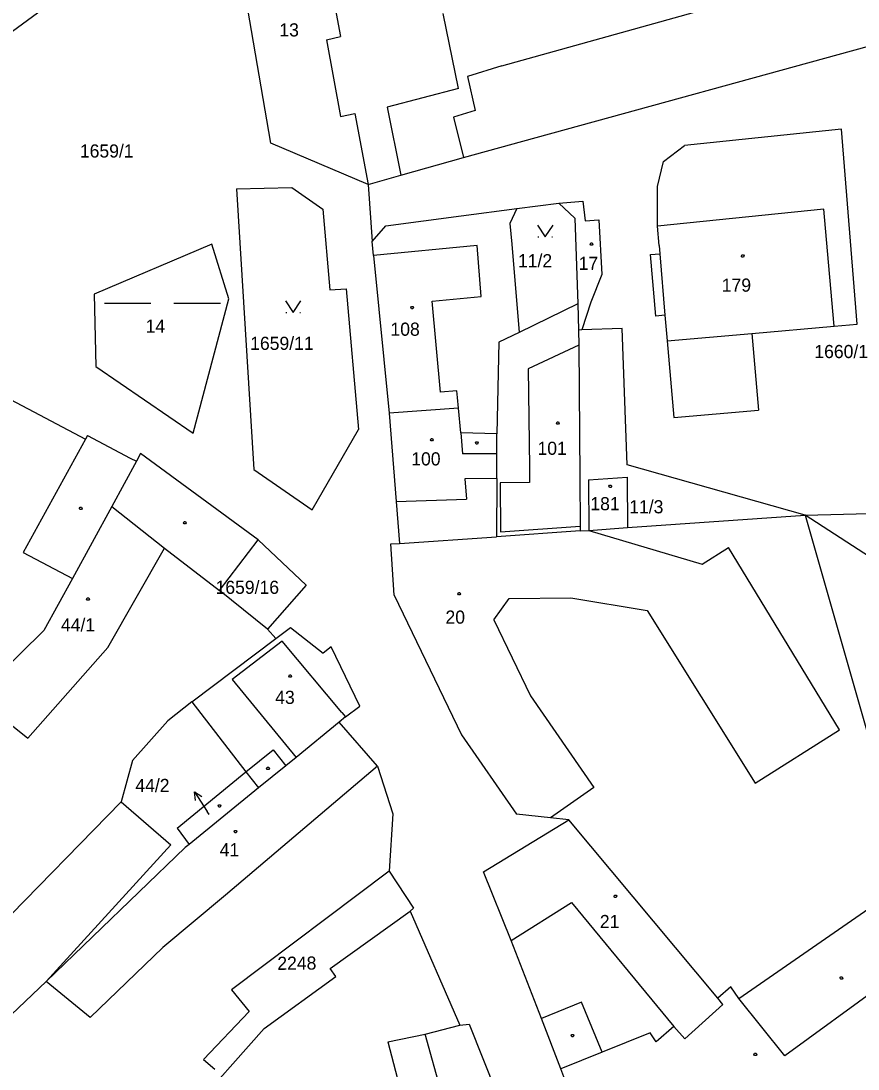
# Model space of a CAD drawing. Extents: x -802857 to -799647, y -1020285 to -1015884.
# Drawn here: x -801501.8 to -801393.5, y -1017775.9 to -1017640.2 of the extents above; entities that cross this region are included whole.
import ezdxf

# ---------------------------------------------------------------- set-up
doc = ezdxf.new("R2010")
doc.units = 0
for name, color, linetype in [('Default', 7, 'Continuous'), ('KN_HRANICE', 7, 'Continuous'), ('KN_KULTURY', 7, 'Continuous'), ('KN_PARCELY', 7, 'Continuous'), ('KN_SLUCKY', 7, 'Continuous')]:
    doc.layers.add(name, color=color, linetype=linetype)

# ---------------------------------------------------------------- blocks, each defined once
blk = doc.blocks.new('314')
at = {"layer": 'Default'}
for p, q in [((-0.95, 0), (-0.85, 0)), ((0.85, 0), (0.95, 0))]:
    blk.add_line(p, q, dxfattribs=at)
blk.add_lwpolyline([(-1, 1.5), (0, 0), (1, 1.5)], dxfattribs=at)
blk = doc.blocks.new('NAHRADNI_SYMBOL')
at = {"layer": 'Default'}
blk.add_lwpolyline([(0.09, 0.15), (0.18, 0), (0.09, -0.15), (-0.09, -0.15), (-0.18, 0), (-0.09, 0.15), (0.09, 0.15)], dxfattribs=at)
blk = doc.blocks.new('803')
at = {"layer": 'Default'}
for p, q in [((-7.5, 0), (-1.5, 0)), ((1.5, 0), (7.5, 0))]:
    blk.add_line(p, q, dxfattribs=at)
blk = doc.blocks.new('10292')
at = {"layer": 'Default'}
blk.add_line((0, 3), (0, 0), dxfattribs=at)
blk.add_lwpolyline([(-0.5, 2), (0, 3), (0.5, 2)], dxfattribs=at)
blk = doc.blocks.new('402')
at = {"layer": 'Default'}
blk.add_lwpolyline([(0.09, 0.15), (0.18, 0), (0.09, -0.15), (-0.09, -0.15), (-0.18, 0), (-0.09, 0.15), (0.09, 0.15)], dxfattribs=at)

msp = doc.modelspace()

# ---------------------------------------------------------------- linework, layer by layer
at = {"layer": 'KN_HRANICE'}
for p, q in [((-801439.56, -1017646.05), (-801339.49, -1017618.1)), ((-801464.55, -1017620.59), (-801460.47, -1017642.27)), ((-801469.47, -1017656.08), (-801475.13, -1017623.23)), ((-801436.88, -1017655.78), (-801344.28, -1017630.37)), ((-801499.03, -1017638.78), (-801510.49, -1017647.16)), ((-801445.17, -1017648.98), (-801447.15, -1017639.26)), ((-801462.26, -1017642.67), (-801460.47, -1017642.27)), ((-801462.26, -1017642.67), (-801460.46, -1017652.61)), ((-801439.56, -1017646.05), (-801444.04, -1017647.45)), ((-801444.04, -1017647.45), (-801443.02, -1017651.83)), ((-801445.17, -1017648.98), (-801454.4, -1017651.38)), ((-801460.46, -1017652.61), (-801458.6, -1017652.2)), ((-801458.6, -1017652.2), (-801456.87, -1017661.39)), ((-801454.4, -1017651.38), (-801452.65, -1017660.21)), ((-801443.02, -1017651.83), (-801445.83, -1017652.69)), ((-801445.83, -1017652.69), (-801444.54, -1017657.93)), ((-801395.62, -1017654.26), (-801415.94, -1017656.38)), ((-801393.58, -1017679.48), (-801395.62, -1017654.26)), ((-801456.87, -1017661.39), (-801469.47, -1017656.08)), ((-801444.54, -1017657.93), (-801436.88, -1017655.78)), ((-801418.65, -1017658.44), (-801415.94, -1017656.38)), ((-801452.65, -1017660.21), (-801444.54, -1017657.93)), ((-801419.45, -1017661.66), (-801418.65, -1017658.44)), ((-801456.87, -1017661.39), (-801452.65, -1017660.21)), ((-801473.9, -1017661.96), (-801466.75, -1017661.81)), ((-801473.9, -1017661.96), (-801471.67, -1017698.28)), ((-801466.75, -1017661.81), (-801462.75, -1017664.58)), ((-801456.87, -1017661.39), (-801456.38, -1017668.8)), ((-801419.44, -1017665.46), (-801419.45, -1017661.66)), ((-801462.75, -1017664.58), (-801461.83, -1017675.05)), ((-801444.82, -1017665.47), (-801437.64, -1017664.53)), ((-801437.64, -1017664.53), (-801438.53, -1017666.45)), ((-801437.64, -1017664.53), (-801432.19, -1017663.81)), ((-801432.19, -1017663.81), (-801429.11, -1017663.56)), ((-801432.19, -1017663.81), (-801430.14, -1017665.75)), ((-801429.11, -1017663.56), (-801428.81, -1017666.12)), ((-801454.57, -1017666.75), (-801444.82, -1017665.47)), ((-801430.14, -1017665.75), (-801429.73, -1017676.83)), ((-801428.81, -1017666.12), (-801427.01, -1017665.96)), ((-801427.01, -1017665.96), (-801426.65, -1017673.07)), ((-801419.44, -1017666.81), (-801419.44, -1017665.46)), ((-801456.38, -1017668.8), (-801454.57, -1017666.75)), ((-801438.53, -1017666.45), (-801438.3, -1017669.15)), ((-801419.23, -1017669.3), (-801419.44, -1017666.81)), ((-801456.2, -1017670.59), (-801456.38, -1017668.8)), ((-801477.13, -1017669.12), (-801492.36, -1017675.58)), ((-801474.9, -1017676.19), (-801477.13, -1017669.12)), ((-801438.3, -1017669.15), (-801437.35, -1017680.56)), ((-801419.23, -1017669.3), (-801419.14, -1017670.36)), ((-801456.2, -1017670.59), (-801454.16, -1017690.99)), ((-801420.34, -1017670.46), (-801419.14, -1017670.36)), ((-801419.66, -1017678.43), (-801420.34, -1017670.46)), ((-801426.65, -1017673.07), (-801428.05, -1017676.64)), ((-801492.36, -1017675.58), (-801492.13, -1017684.97)), ((-801461.83, -1017675.05), (-801459.74, -1017674.9)), ((-801459.74, -1017674.9), (-801458.13, -1017693.12)), ((-801479.51, -1017693.58), (-801474.9, -1017676.19)), ((-801429.73, -1017676.83), (-801437.35, -1017680.56)), ((-801429.73, -1017676.83), (-801429.65, -1017680.25)), ((-801428.05, -1017676.64), (-801429.23, -1017680.23)), ((-801418.46, -1017678.33), (-801419.66, -1017678.43)), ((-801418.46, -1017678.33), (-801418.18, -1017681.62)), ((-801407.22, -1017680.67), (-801396.57, -1017679.74)), ((-801396.57, -1017679.74), (-801393.58, -1017679.48)), ((-801437.35, -1017680.56), (-801439.98, -1017681.83)), ((-801429.23, -1017680.23), (-801429.65, -1017680.25)), ((-801429.65, -1017680.25), (-801429.62, -1017682.21)), ((-801424.02, -1017680.04), (-801429.23, -1017680.23)), ((-801423.35, -1017697.69), (-801424.02, -1017680.04)), ((-801407.22, -1017680.67), (-801406.35, -1017690.63)), ((-801439.98, -1017681.83), (-801440.22, -1017693.66)), ((-801429.62, -1017682.21), (-801429.47, -1017699.34)), ((-801418.18, -1017681.62), (-801417.31, -1017691.58)), ((-801492.13, -1017684.97), (-801479.51, -1017693.58)), ((-801503.16, -1017689.24), (-801493.48, -1017694.38)), ((-801445.17, -1017690.35), (-801454.16, -1017690.99)), ((-801444.9, -1017693.53), (-801445.17, -1017690.35)), ((-801417.31, -1017691.58), (-801406.35, -1017690.63)), ((-801454.16, -1017690.99), (-801453.25, -1017702.44)), ((-801464.13, -1017703.51), (-801458.13, -1017693.12)), ((-801493.2, -1017693.88), (-801493.48, -1017694.38)), ((-801493.2, -1017693.88), (-801487.66, -1017696.81)), ((-801444.9, -1017693.53), (-801444.66, -1017696.24)), ((-801440.21, -1017696.24), (-801440.22, -1017693.66)), ((-801486.87, -1017697.21), (-801490.05, -1017703.09)), ((-801487.66, -1017696.81), (-801486.87, -1017697.21)), ((-801486.33, -1017696.21), (-801486.87, -1017697.21)), ((-801471.12, -1017707.39), (-801486.33, -1017696.21)), ((-801440.21, -1017696.24), (-801444.66, -1017696.24)), ((-801440.22, -1017698), (-801440.21, -1017696.24)), ((-801471.67, -1017698.28), (-801464.13, -1017703.51)), ((-801440.23, -1017699.44), (-801440.22, -1017698)), ((-801400.33, -1017704.19), (-801423.35, -1017697.69)), ((-801440.23, -1017699.44), (-801440.25, -1017706.98)), ((-801429.47, -1017699.34), (-801429.43, -1017705.64)), ((-801428.36, -1017699.63), (-801423.34, -1017699.29)), ((-801428.36, -1017699.63), (-801428.32, -1017706.16)), ((-801423.34, -1017699.29), (-801423.32, -1017705.79)), ((-801453.25, -1017702.44), (-801452.8, -1017707.85)), ((-801490.05, -1017703.09), (-801495.16, -1017712.38)), ((-801423.32, -1017705.79), (-801400.33, -1017704.19)), ((-801400.33, -1017704.19), (-801384.4, -1017703.77)), ((-801400.33, -1017704.19), (-801386.84, -1017751.44)), ((-801380.71, -1017716.88), (-801400.33, -1017704.19)), ((-801429.43, -1017706.24), (-801440.25, -1017706.98)), ((-801429.43, -1017705.64), (-801429.43, -1017706.24)), ((-801429.43, -1017706.24), (-801428.32, -1017706.16)), ((-801428.32, -1017706.16), (-801423.32, -1017705.79)), ((-801476.12, -1017713.95), (-801471.12, -1017707.39)), ((-801471.12, -1017707.39), (-801464.92, -1017713.27)), ((-801453.96, -1017707.92), (-801452.8, -1017707.85)), ((-801453.53, -1017714.55), (-801453.96, -1017707.92)), ((-801452.8, -1017707.85), (-801440.25, -1017706.98)), ((-801495.16, -1017712.38), (-801498.85, -1017719.1)), ((-801464.92, -1017713.27), (-801469.89, -1017718.97)), ((-801469.89, -1017718.97), (-801476.12, -1017713.95)), ((-801453.53, -1017714.55), (-801444.8, -1017732.63)), ((-801498.85, -1017719.1), (-801507.61, -1017727.7)), ((-801469.89, -1017718.97), (-801468.81, -1017720.17)), ((-801468.81, -1017720.17), (-801466.92, -1017718.75)), ((-801466.92, -1017718.75), (-801462.68, -1017722.04)), ((-801479.69, -1017728.34), (-801468.81, -1017720.17)), ((-801461.67, -1017721.24), (-801462.68, -1017722.04)), ((-801457.95, -1017728.92), (-801461.67, -1017721.24)), ((-801479.69, -1017728.34), (-801482.8, -1017730.8)), ((-801479.69, -1017728.34), (-801472.69, -1017737.41)), ((-801459.8, -1017730.31), (-801457.95, -1017728.92)), ((-801482.8, -1017730.8), (-801487.38, -1017735.95)), ((-801460.64, -1017731), (-801466.21, -1017735.54)), ((-801459.8, -1017730.31), (-801460.64, -1017731)), ((-801455.66, -1017736.67), (-801460.64, -1017731)), ((-801444.8, -1017732.63), (-801437.69, -1017742.9)), ((-801487.38, -1017735.95), (-801488.83, -1017741.31)), ((-801467.55, -1017736.63), (-801471.07, -1017739.5)), ((-801466.21, -1017735.54), (-801467.55, -1017736.63)), ((-801455.66, -1017736.67), (-801453.7, -1017742.86)), ((-801472.69, -1017737.41), (-801471.07, -1017739.5)), ((-801471.07, -1017739.5), (-801480.05, -1017746.82)), ((-801488.83, -1017741.31), (-801482.4, -1017746.87)), ((-801453.7, -1017742.86), (-801454.14, -1017750.26)), ((-801433.27, -1017743.36), (-801437.69, -1017742.9)), ((-801430.91, -1017743.61), (-801433.27, -1017743.36)), ((-801441.93, -1017750.37), (-801430.91, -1017743.61)), ((-801411.64, -1017766.72), (-801430.91, -1017743.61)), ((-801482.4, -1017746.87), (-801498.56, -1017764.53)), ((-801480.55, -1017747.22), (-801498.56, -1017764.53)), ((-801480.05, -1017746.82), (-801480.55, -1017747.22)), ((-801454.14, -1017750.26), (-801474.58, -1017765.6)), ((-801454.14, -1017750.26), (-801451, -1017755.07)), ((-801438.38, -1017759.22), (-801441.93, -1017750.37)), ((-801451, -1017755.07), (-801451.46, -1017755.42)), ((-801451.46, -1017755.42), (-801445.03, -1017770.19)), ((-801434.46, -1017769.34), (-801438.38, -1017759.22)), ((-801384.3, -1017760.57), (-801402.96, -1017774.15)), ((-801498.56, -1017764.53), (-801505.81, -1017771.41)), ((-801409.95, -1017765.22), (-801411.64, -1017766.72)), ((-801408.92, -1017766.74), (-801409.95, -1017765.22)), ((-801474.58, -1017765.6), (-801472.28, -1017768.42)), ((-801415.89, -1017771.96), (-801410.96, -1017767.53)), ((-801410.96, -1017767.53), (-801411.64, -1017766.72)), ((-801402.96, -1017774.15), (-801408.92, -1017766.74)), ((-801472.28, -1017768.42), (-801478.17, -1017774.62)), ((-801449.49, -1017771.37), (-801445.03, -1017770.19)), ((-801445.03, -1017770.19), (-801443.81, -1017770.05)), ((-801443.81, -1017770.05), (-801439.99, -1017779.67)), ((-801431.94, -1017775.86), (-801434.46, -1017769.34)), ((-801417.3, -1017770.37), (-801419.61, -1017772.37)), ((-801417.3, -1017770.37), (-801415.89, -1017771.96)), ((-801454.34, -1017772.35), (-801449.49, -1017771.37)), ((-801420.38, -1017771.18), (-801426.59, -1017773.69)), ((-801419.61, -1017772.37), (-801420.38, -1017771.18)), ((-801454.34, -1017772.35), (-801451.15, -1017784.39)), ((-801478.17, -1017774.62), (-801476.71, -1017775.88)), ((-801426.59, -1017773.69), (-801431.94, -1017775.86)), ((-801428.76, -1017784.1), (-801431.94, -1017775.86))]:
    msp.add_line(p, q, dxfattribs=at)
msp.add_lwpolyline([(-801480.11, -1017781.68), (-801470.32, -1017770.64), (-801461.06, -1017763.9), (-801461.81, -1017762.88), (-801451.46, -1017755.42)], dxfattribs=at)
at = {"layer": 'KN_PARCELY'}
msp.add_line((-801477.47, -1017742.93), (-801477.73, -1017742.53), dxfattribs=at)
at = {"layer": 'KN_SLUCKY'}
for p, q in [((-801397.89, -1017664.58), (-801419.44, -1017666.81)), ((-801397.68, -1017667.07), (-801397.89, -1017664.58)), ((-801396.57, -1017679.74), (-801397.68, -1017667.07)), ((-801442.79, -1017669.32), (-801456.2, -1017670.59)), ((-801442.23, -1017675.92), (-801442.79, -1017669.32)), ((-801419.14, -1017670.36), (-801418.46, -1017678.33)), ((-801448.61, -1017676.52), (-801442.23, -1017675.92)), ((-801447.51, -1017688.29), (-801448.61, -1017676.52)), ((-801418.18, -1017681.62), (-801407.22, -1017680.67)), ((-801429.62, -1017682.21), (-801436.16, -1017685.24)), ((-801436.16, -1017685.24), (-801436.01, -1017697.99)), ((-801445.41, -1017688.09), (-801447.51, -1017688.29)), ((-801445.33, -1017688.99), (-801445.41, -1017688.09)), ((-801445.17, -1017690.35), (-801445.33, -1017688.99)), ((-801493.48, -1017694.38), (-801501.51, -1017709.02)), ((-801440.22, -1017693.66), (-801444.9, -1017693.53)), ((-801436.01, -1017697.99), (-801435.99, -1017699.99)), ((-801440.23, -1017699.44), (-801444.38, -1017699.5)), ((-801444.38, -1017699.5), (-801444.15, -1017702.13)), ((-801435.99, -1017699.99), (-801439.78, -1017700.01)), ((-801439.78, -1017700.01), (-801439.74, -1017706.34)), ((-801453.25, -1017702.44), (-801444.15, -1017702.13)), ((-801490.05, -1017703.09), (-801483.23, -1017708.46)), ((-801439.74, -1017706.34), (-801429.43, -1017705.64)), ((-801428.32, -1017706.16), (-801413.65, -1017710.55)), ((-801501.51, -1017709.02), (-801495.16, -1017712.38)), ((-801490.57, -1017721.33), (-801483.23, -1017708.46)), ((-801483.23, -1017708.46), (-801476.12, -1017713.95)), ((-801413.65, -1017710.55), (-801410.25, -1017708.4)), ((-801395.86, -1017731.97), (-801410.25, -1017708.4)), ((-801440.62, -1017717.72), (-801438.64, -1017714.97)), ((-801438.64, -1017714.97), (-801430.65, -1017714.89)), ((-801430.65, -1017714.89), (-801420.77, -1017716.55)), ((-801440.62, -1017717.72), (-801435.87, -1017727.56)), ((-801420.77, -1017716.55), (-801406.77, -1017738.86)), ((-801500.92, -1017733.04), (-801490.57, -1017721.33)), ((-801468, -1017720.51), (-801474.46, -1017725.46)), ((-801460.29, -1017729.75), (-801468, -1017720.51)), ((-801474.46, -1017725.46), (-801466.21, -1017735.54)), ((-801507.61, -1017727.7), (-801500.92, -1017733.04)), ((-801435.87, -1017727.56), (-801427.66, -1017739.42)), ((-801460.29, -1017729.75), (-801459.8, -1017730.31)), ((-801406.77, -1017738.86), (-801395.86, -1017731.97)), ((-801472.69, -1017737.41), (-801469.19, -1017734.55)), ((-801469.19, -1017734.55), (-801467.55, -1017736.63)), ((-801455.66, -1017736.67), (-801475.36, -1017753.35)), ((-801481.58, -1017744.68), (-801472.69, -1017737.41)), ((-801427.66, -1017739.42), (-801433.27, -1017743.36)), ((-801506.09, -1017758.92), (-801488.83, -1017741.31)), ((-801481.58, -1017744.68), (-801480.05, -1017746.82)), ((-801408.92, -1017766.74), (-801386.84, -1017751.44)), ((-801475.36, -1017753.35), (-801483.45, -1017760.14)), ((-801438.38, -1017759.22), (-801430.55, -1017754.32)), ((-801430.55, -1017754.32), (-801417.3, -1017770.37)), ((-801483.45, -1017760.14), (-801492.84, -1017769.18)), ((-801492.84, -1017769.18), (-801498.56, -1017764.53)), ((-801429.27, -1017767.23), (-801434.46, -1017769.34)), ((-801426.59, -1017773.69), (-801429.27, -1017767.23)), ((-801446.22, -1017783.09), (-801449.49, -1017771.37))]:
    msp.add_line(p, q, dxfattribs=at)

# ---------------------------------------------------------------- block references
at = {"layer": 'KN_KULTURY'}
for name, p in [('314', (-801433.95, -1017668.16)), ('NAHRADNI_SYMBOL', (-801427.98, -1017669.12)), ('402', (-801408.4, -1017670.64)), ('803', (-801483.51, -1017676.77)), ('314', (-801466.57, -1017677.96)), ('402', (-801451.17, -1017677.33)), ('402', (-801432.33, -1017692.29)), ('402', (-801448.64, -1017694.44)), ('402', (-801442.8, -1017694.84)), ('402', (-801425.54, -1017700.45)), ('402', (-801494.08, -1017703.33)), ('402', (-801480.6, -1017705.17)), ('402', (-801493.14, -1017715.06)), ('402', (-801445.11, -1017714.36)), ('402', (-801466.98, -1017725.01)), ('402', (-801469.84, -1017736.96)), ('402', (-801476.11, -1017741.82)), ('402', (-801474.04, -1017745.14)), ('402', (-801424.88, -1017753.52)), ('402', (-801395.63, -1017764.09)), ('402', (-801430.42, -1017771.55)), ('NAHRADNI_SYMBOL', (-801406.77, -1017773.98))]:
    msp.add_blockref(name, p, dxfattribs=at)
at = {"layer": 'KN_PARCELY', "rotation": 33.116960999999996}
msp.add_blockref('10292', (-801477.73, -1017742.53), dxfattribs=at)

# ---------------------------------------------------------------- texts
at = {"layer": 'KN_PARCELY'}
for s, height, p in [('13', 1.7, (-801468.37, -1017642.25)), ('1659/1', 1.7, (-801494.19, -1017657.92)), ('11/2', 1.7, (-801437.49, -1017672.12)), ('17', 1.7, (-801429.64, -1017672.46)), ('179', 1.7, (-801411.11, -1017675.28)), ('14', 1.7, (-801485.68, -1017680.58)), ('108', 1.7, (-801453.99, -1017680.98)), ('1659/11', 1.7, (-801472.15, -1017682.81)), ('1660/1', 1.7, (-801399.13, -1017683.87)), ('101', 1.7, (-801434.96, -1017696.39)), ('100', 1.7, (-801451.3, -1017697.76)), ('181', 1.7, (-801428.12, -1017703.56)), ('11/3', 1.7, (-801423.09, -1017703.96)), ('1659/16', 1.7, (-801476.63, -1017714.38)), ('44/1', 1.7, (-801496.64, -1017719.24)), ('20', 1.7, (-801446.87, -1017718.24)), ('43', 1.7, (-801468.91, -1017728.62)), ('44/2', 1.7, (-801487.01, -1017740.02)), ('44/2', 0.1, (-801477.67, -1017742.93)), ('41', 1.7, (-801476.09, -1017748.34)), ('21', 1.7, (-801426.89, -1017757.63))]:
    msp.add_text(s, height=height, dxfattribs=at).set_placement(p)
msp.add_text('2248', height=1.7, rotation=0.458, dxfattribs=at).set_placement((-801468.63, -1017763.04))

doc.saveas('drawing.dxf')
